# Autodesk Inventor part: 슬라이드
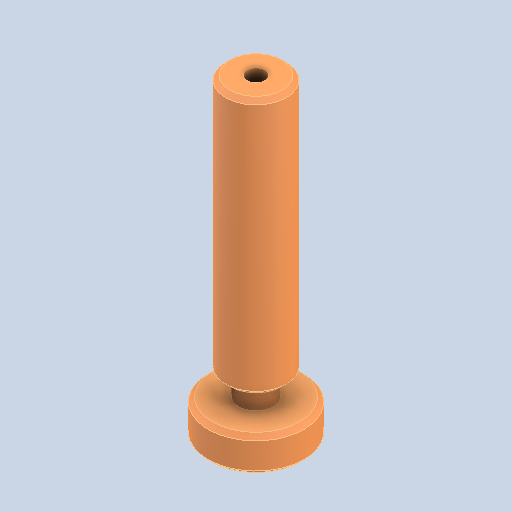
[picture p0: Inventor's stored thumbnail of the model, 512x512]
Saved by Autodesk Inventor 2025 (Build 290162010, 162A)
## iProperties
Created: 2024-07
Part Number: 슬라이드
Material: 강철, 연강
Document SubType Name: Modeling
Designer: Admin
Density: 7.86 g/cm^3
Appearance: 기본값
Author: jhkim
Sending System: Autodesk Inventor 2025
Preprocessor: ST-DEVELOPER v20
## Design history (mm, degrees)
feature "솔리드1"
node "솔리드2"
